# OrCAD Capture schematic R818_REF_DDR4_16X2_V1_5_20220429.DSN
size A3; title: R818-DDR4; rev: 0.1; note: DDR4 16X2
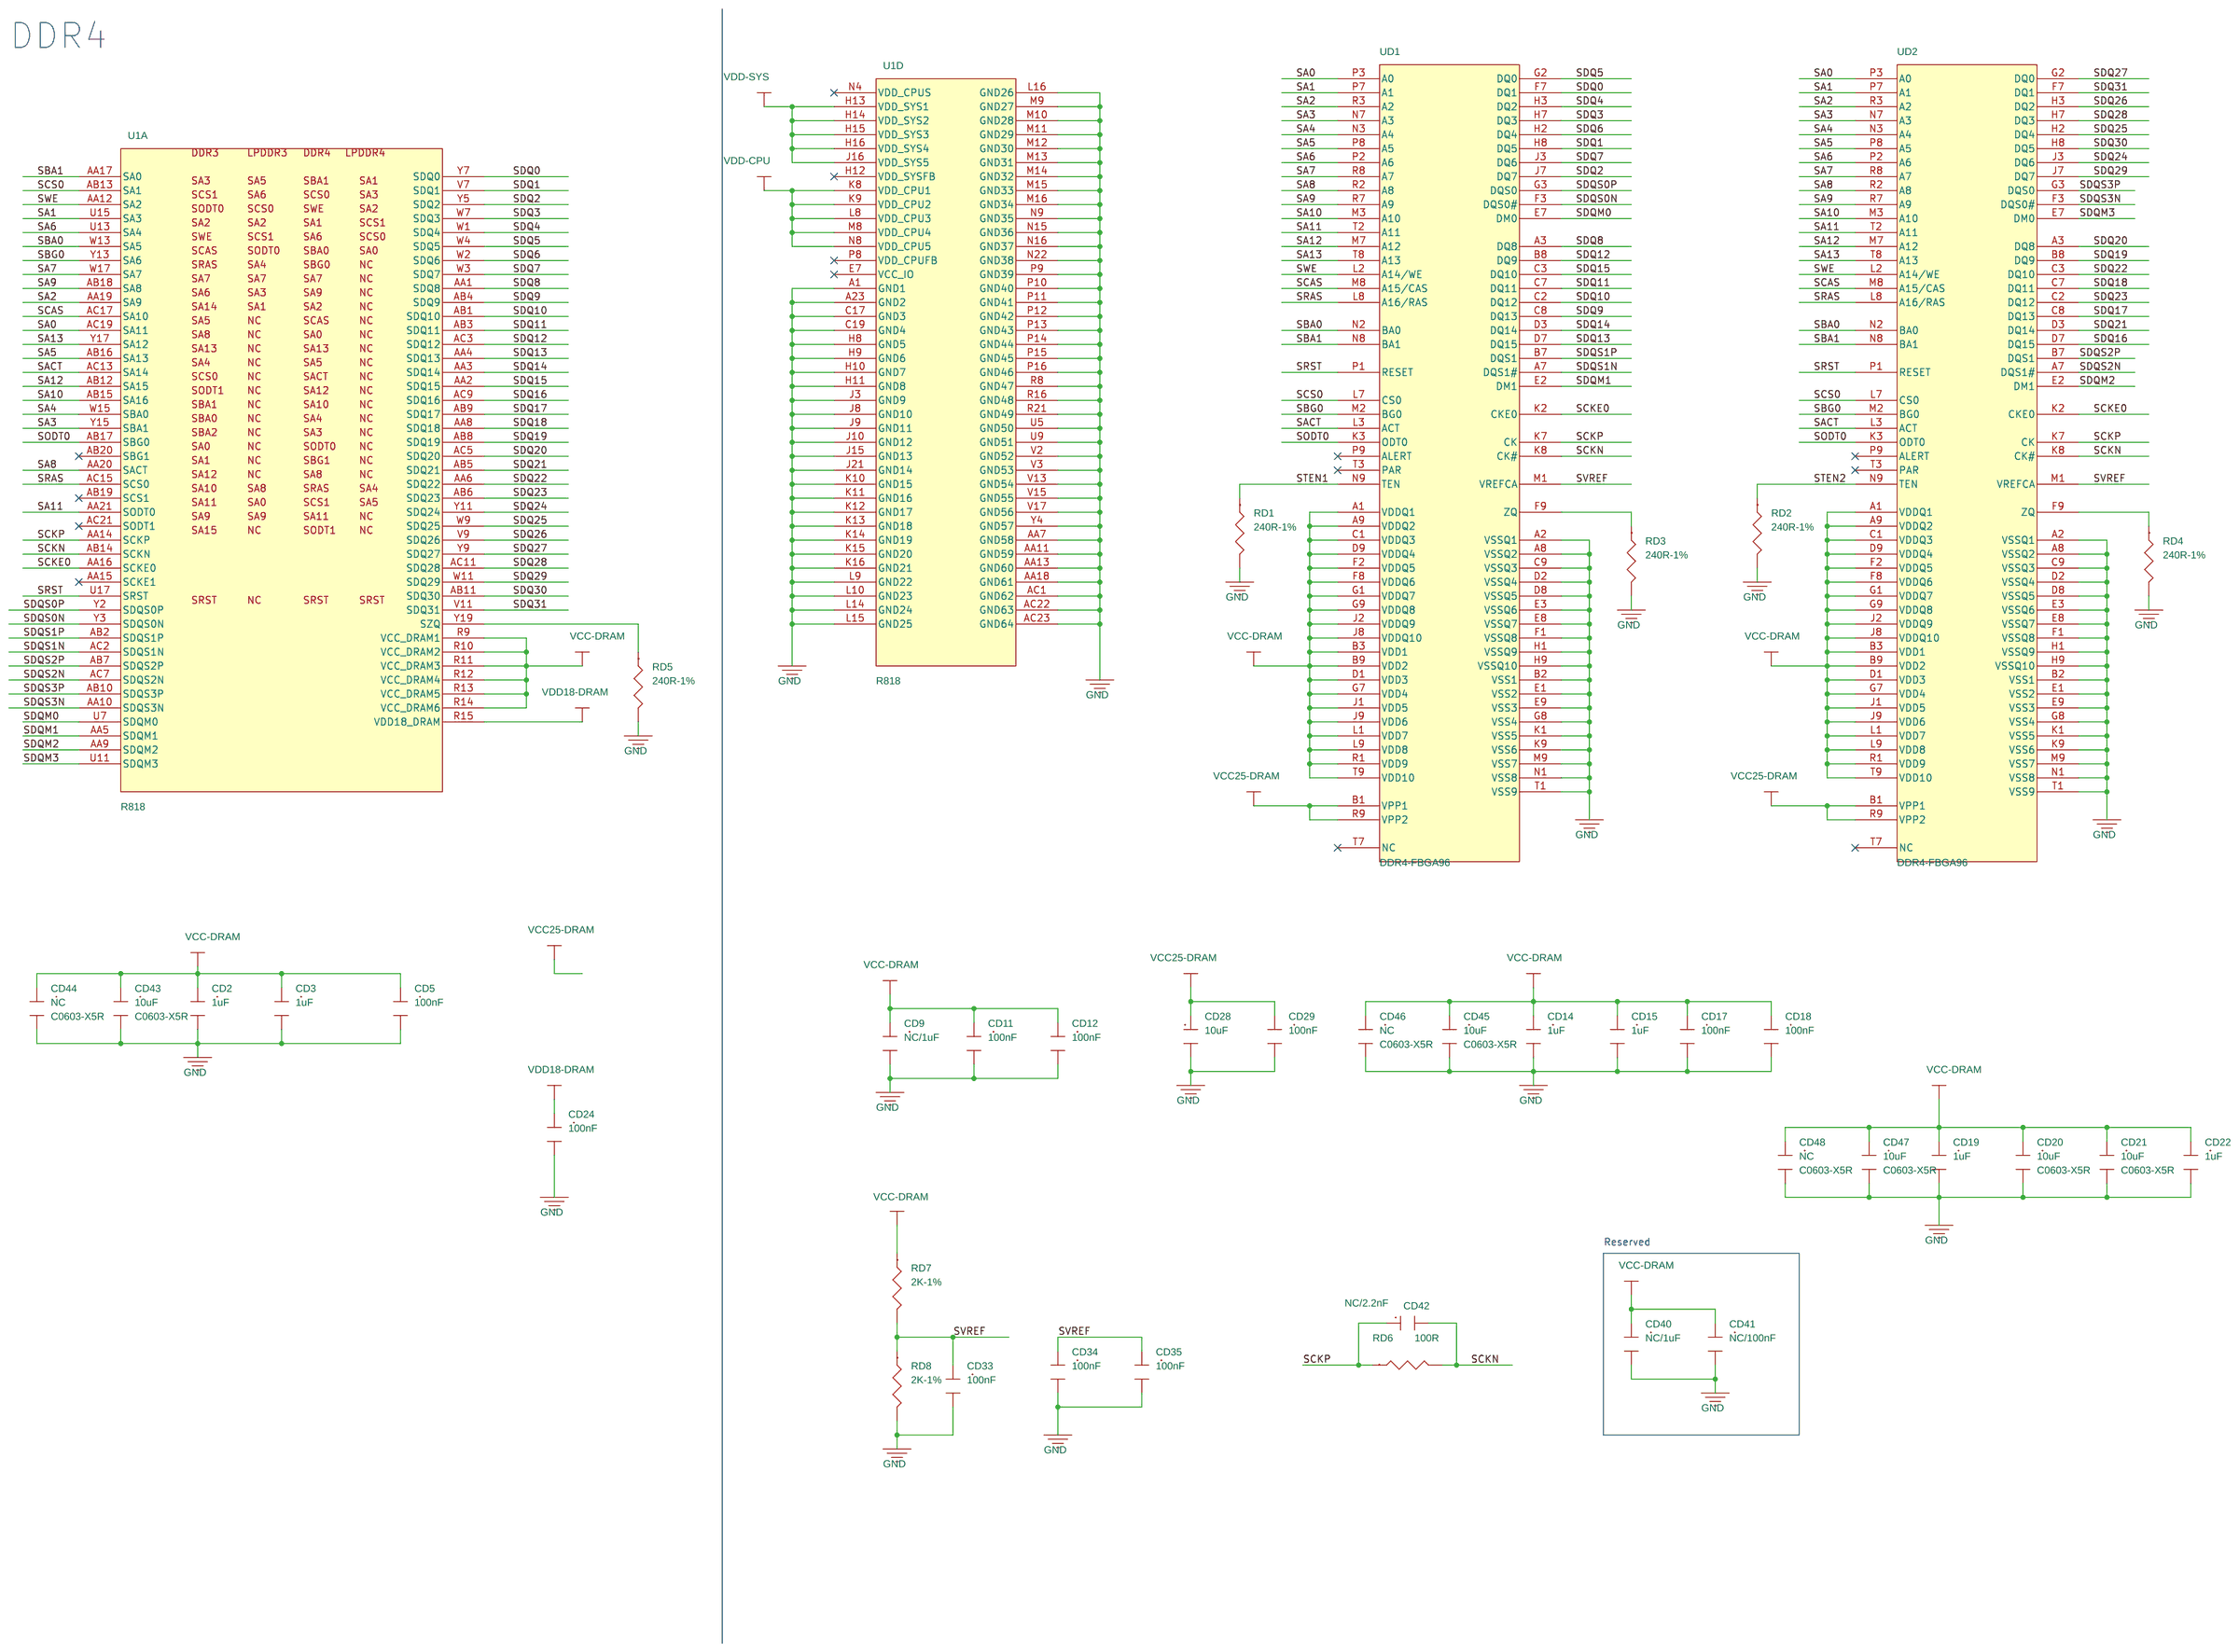
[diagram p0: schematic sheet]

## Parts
CD2  1uF  [C0402]
CD3  1uF  [C0402]
CD5  100nF  [C0402]
CD9  NC/1uF  [C0402]
CD11  100nF  [C0402]
CD12  100nF  [C0402]
CD14  1uF  [C0402]
CD15  1uF  [C0402]
CD17  100nF  [C0402]
CD18  100nF  [C0402]
CD19  1uF  [C0402]
CD20  10uF  [C0603]
CD21  10uF  [C0603]
CD22  1uF  [C0402]
CD24  100nF  [C0402]
CD28  10uF  [C0603]
CD29  100nF  [C0402]
CD33  100nF  [C0402]
CD34  100nF  [C0402]
CD35  100nF  [C0402]
CD40  NC/1uF  [C0402]
CD41  NC/100nF  [C0402]
CD42  NC/2.2nF  [C0402]
CD43  10uF  [C0603]
CD44  NC  [C0603]
CD45  10uF  [C0603]
CD46  NC  [C0603]
CD47  10uF  [C0603]
CD48  NC  [C0603]
RD1  240R-1%  [R0402]
RD2  240R-1%  [R0402]
RD3  240R-1%  [R0402]
RD4  240R-1%  [R0402]
RD5  240R-1%  [R0402]
RD6  100R  [R0402]
RD7  2K-1%  [R0402]
RD8  2K-1%  [R0402]
U1  R818  [BGA346P50B1200_1200H114]  (sections A,D)
UD1  DDR4-FBGA96  [BGA96P80B1000_1400H120]
UD2  DDR4-FBGA96  [BGA96P80B1000_1400H120]

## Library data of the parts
CD2 CD3 CD5 CD9 CD11 CD12 CD14 CD15 CD17-CD19 CD22 CD24 CD29 CD33-CD35 CD40-CD42 = C-C0402-X5R
CD20 CD21 CD43-CD48 = C-C0402-X5R: Parameter: C0603-X5R
CD28 = C-C0603-X5R
RD1-RD5 RD7 RD8 = R-R0402-1%
RD6 = R-R0402-5%
U1 = R818-BGA-20200509
UD1 UD2 = DDR4-FBGA96

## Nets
GND: CD2.2 CD3.2 CD5.2 CD9.2 CD11.2 CD12.2 CD14.2 CD15.2 CD17.2 CD18.2 CD19.2 CD20.2 CD21.2 CD22.2 CD24.2 CD28.2 CD29.2 CD33.2 CD34.2 CD35.2 CD40.2 CD41.2 CD43.2 CD44.2 CD45.2 CD46.2 CD47.2 CD48.2 RD1.2 RD2.2 RD3.2 RD4.2 RD5.2 RD8.2 U1.A1(GND1) U1.A23(GND2) U1.AA7(GND58) U1.AA11(GND59) U1.AA13(GND60) U1.AA18(GND61) U1.AC1(GND62) U1.AC22(GND63) U1.AC23(GND64) U1.C17(GND3) U1.C19(GND4) U1.H8(GND5) U1.H9(GND6) U1.H10(GND7) U1.H11(GND8) U1.J3(GND9) U1.J8(GND10) U1.J9(GND11) U1.J10(GND12) U1.J15(GND13) U1.J21(GND14) U1.K10(GND15) U1.K11(GND16) U1.K12(GND17) U1.K13(GND18) U1.K14(GND19) U1.K15(GND20) U1.K16(GND21) U1.L9(GND22) U1.L10(GND23) U1.L14(GND24) U1.L15(GND25) U1.L16(GND26) U1.M9(GND27) U1.M10(GND28) U1.M11(GND29) U1.M12(GND30) U1.M13(GND31) U1.M14(GND32) U1.M15(GND33) U1.M16(GND34) U1.N9(GND35) U1.N15(GND36) U1.N16(GND37) U1.N22(GND38) U1.P9(GND39) U1.P10(GND40) U1.P11(GND41) U1.P12(GND42) U1.P13(GND43) U1.P14(GND44) U1.P15(GND45) U1.P16(GND46) U1.R8(GND47) U1.R16(GND48) U1.R21(GND49) U1.U5(GND50) U1.U9(GND51) U1.V2(GND52) U1.V3(GND53) U1.V13(GND54) U1.V15(GND55) U1.V17(GND56) U1.Y4(GND57) UD1.A2(VSSQ1) UD1.A8(VSSQ2) UD1.B2(VSS1) UD1.C9(VSSQ3) UD1.D2(VSSQ4) UD1.D8(VSSQ5) UD1.E1(VSS2) UD1.E3(VSSQ6) UD1.E8(VSSQ7) UD1.E9(VSS3) UD1.F1(VSSQ8) UD1.G8(VSS4) UD1.H1(VSSQ9) UD1.H9(VSSQ10) UD1.K1(VSS5) UD1.K9(VSS6) UD1.M9(VSS7) UD1.N1(VSS8) UD1.T1(VSS9) UD2.A2(VSSQ1) UD2.A8(VSSQ2) UD2.B2(VSS1) UD2.C9(VSSQ3) UD2.D2(VSSQ4) UD2.D8(VSSQ5) UD2.E1(VSS2) UD2.E3(VSSQ6) UD2.E8(VSSQ7) UD2.E9(VSS3) UD2.F1(VSSQ8) UD2.G8(VSS4) UD2.H1(VSSQ9) UD2.H9(VSSQ10) UD2.K1(VSS5) UD2.K9(VSS6) UD2.M9(VSS7) UD2.N1(VSS8) UD2.T1(VSS9)
VCC25-DRAM: CD28.1 CD29.1 UD1.B1(VPP1) UD1.R9(VPP2) UD2.B1(VPP1) UD2.R9(VPP2)
VCC-DRAM: CD2.1 CD3.1 CD5.1 CD9.1 CD11.1 CD12.1 CD14.1 CD15.1 CD17.1 CD18.1 CD19.1 CD20.1 CD21.1 CD22.1 CD40.1 CD41.1 CD43.1 CD44.1 CD45.1 CD46.1 CD47.1 CD48.1 RD7.1 U1.R9(VCC_DRAM1) U1.R10(VCC_DRAM2) U1.R11(VCC_DRAM3) U1.R12(VCC_DRAM4) U1.R13(VCC_DRAM5) U1.R14(VCC_DRAM6) UD1.A1(VDDQ1) UD1.A9(VDDQ2) UD1.B3(VDD1) UD1.B9(VDD2) UD1.C1(VDDQ3) UD1.D1(VDD3) UD1.D9(VDDQ4) UD1.F2(VDDQ5) UD1.F8(VDDQ6) UD1.G1(VDDQ7) UD1.G7(VDD4) UD1.G9(VDDQ8) UD1.J1(VDD5) UD1.J2(VDDQ9) UD1.J8(VDDQ10) UD1.J9(VDD6) UD1.L1(VDD7) UD1.L9(VDD8) UD1.R1(VDD9) UD1.T9(VDD10) UD2.A1(VDDQ1) UD2.A9(VDDQ2) UD2.B3(VDD1) UD2.B9(VDD2) UD2.C1(VDDQ3) UD2.D1(VDD3) UD2.D9(VDDQ4) UD2.F2(VDDQ5) UD2.F8(VDDQ6) UD2.G1(VDDQ7) UD2.G7(VDD4) UD2.G9(VDDQ8) UD2.J1(VDD5) UD2.J2(VDDQ9) UD2.J8(VDDQ10) UD2.J9(VDD6) UD2.L1(VDD7) UD2.L9(VDD8) UD2.R1(VDD9) UD2.T9(VDD10)
VDD18-DRAM: CD24.1 U1.R15(VDD18_DRAM)
VDD-CPU: U1.K8(VDD_CPU1) U1.K9(VDD_CPU2) U1.L8(VDD_CPU3) U1.M8(VDD_CPU4) U1.N8(VDD_CPU5)
VDD-SYS: U1.H13(VDD_SYS1) U1.H14(VDD_SYS2) U1.H15(VDD_SYS3) U1.H16(VDD_SYS4) U1.J16(VDD_SYS5)
SA0: U1.AC19(SA11) UD1.P3(A0) UD2.P3(A0)
SA1: U1.U15(SA3) UD1.P7(A1) UD2.P7(A1)
SA2: U1.AA19(SA9) UD1.R3(A2) UD2.R3(A2)
SA3: U1.Y15(SBA1) UD1.N7(A3) UD2.N7(A3)
SA4: U1.W15(SBA0) UD1.N3(A4) UD2.N3(A4)
SA5: U1.AB16(SA13) UD1.P8(A5) UD2.P8(A5)
SA6: U1.U13(SA4) UD1.P2(A6) UD2.P2(A6)
SA7: U1.W17(SA7) UD1.R8(A7) UD2.R8(A7)
SA8: U1.AA20(SACT) UD1.R2(A8) UD2.R2(A8)
SA9: U1.AB18(SA8) UD1.R7(A9) UD2.R7(A9)
SA10: U1.AB15(SA16) UD1.M3(A10) UD2.M3(A10)
SA11: U1.AA21(SODT0) UD1.T2(A11) UD2.T2(A11)
SA12: U1.AB12(SA15) UD1.M7(A12) UD2.M7(A12)
SA13: U1.Y17(SA12) UD1.T8(A13) UD2.T8(A13)
SACT: U1.AC13(SA14) UD1.L3(ACT) UD2.L3(ACT)
SBA0: U1.W13(SA5) UD1.N2(BA0) UD2.N2(BA0)
SBA1: U1.AA17(SA0) UD1.N8(BA1) UD2.N8(BA1)
SBG0: U1.Y13(SA6) UD1.M2(BG0) UD2.M2(BG0)
SCAS: U1.AC17(SA10) UD1.M8(A15/CAS) UD2.M8(A15/CAS)
SCKE0: U1.AA16(SCKE0) UD1.K2(CKE0) UD2.K2(CKE0)
SCKN: CD42.2 RD6.2 U1.AB14(SCKN) UD1.K8(CK#) UD2.K8(CK#)
SCKP: CD42.1 RD6.1 U1.AA14(SCKP) UD1.K7(CK) UD2.K7(CK)
SCS0: U1.AB13(SA1) UD1.L7(CS0) UD2.L7(CS0)
SDQ0: U1.Y7(SDQ0) UD1.F7(DQ1)
SDQ1: U1.V7(SDQ1) UD1.H8(DQ5)
SDQ2: U1.Y5(SDQ2) UD1.J7(DQ7)
SDQ3: U1.W7(SDQ3) UD1.H7(DQ3)
SDQ4: U1.W1(SDQ4) UD1.H3(DQ2)
SDQ5: U1.W4(SDQ5) UD1.G2(DQ0)
SDQ6: U1.W2(SDQ6) UD1.H2(DQ4)
SDQ7: U1.W3(SDQ7) UD1.J3(DQ6)
SDQ8: U1.AA1(SDQ8) UD1.A3(DQ8)
SDQ9: U1.AB4(SDQ9) UD1.C8(DQ13)
SDQ10: U1.AB1(SDQ10) UD1.C2(DQ12)
SDQ11: U1.AB3(SDQ11) UD1.C7(DQ11)
SDQ12: U1.AC3(SDQ12) UD1.B8(DQ9)
SDQ13: U1.AA4(SDQ13) UD1.D7(DQ15)
SDQ14: U1.AA3(SDQ14) UD1.D3(DQ14)
SDQ15: U1.AA2(SDQ15) UD1.C3(DQ10)
SDQ16: U1.AC9(SDQ16) UD2.D7(DQ15)
SDQ17: U1.AB9(SDQ17) UD2.C8(DQ13)
SDQ18: U1.AA8(SDQ18) UD2.C7(DQ11)
SDQ19: U1.AB8(SDQ19) UD2.B8(DQ9)
SDQ20: U1.AC5(SDQ20) UD2.A3(DQ8)
SDQ21: U1.AB5(SDQ21) UD2.D3(DQ14)
SDQ22: U1.AA6(SDQ22) UD2.C3(DQ10)
SDQ23: U1.AB6(SDQ23) UD2.C2(DQ12)
SDQ24: U1.Y11(SDQ24) UD2.J3(DQ6)
SDQ25: U1.W9(SDQ25) UD2.H2(DQ4)
SDQ26: U1.V9(SDQ26) UD2.H3(DQ2)
SDQ27: U1.Y9(SDQ27) UD2.G2(DQ0)
SDQ28: U1.AC11(SDQ28) UD2.H7(DQ3)
SDQ29: U1.W11(SDQ29) UD2.J7(DQ7)
SDQ30: U1.AB11(SDQ30) UD2.H8(DQ5)
SDQ31: U1.V11(SDQ31) UD2.F7(DQ1)
SDQM0: U1.U7(SDQM0) UD1.E7(DM0)
SDQM1: U1.AA5(SDQM1) UD1.E2(DM1)
SDQM2: U1.AA9(SDQM2) UD2.E2(DM1)
SDQM3: U1.U11(SDQM3) UD2.E7(DM0)
SDQS0N: U1.Y3(SDQS0N) UD1.F3(DQS0#)
SDQS0P: U1.Y2(SDQS0P) UD1.G3(DQS0)
SDQS1N: U1.AC2(SDQS1N) UD1.A7(DQS1#)
SDQS1P: U1.AB2(SDQS1P) UD1.B7(DQS1)
SDQS2N: U1.AC7(SDQS2N) UD2.A7(DQS1#)
SDQS2P: U1.AB7(SDQS2P) UD2.B7(DQS1)
SDQS3N: U1.AA10(SDQS3N) UD2.F3(DQS0#)
SDQS3P: U1.AB10(SDQS3P) UD2.G3(DQS0)
SODT0: U1.AB17(SBG0) UD1.K3(ODT0) UD2.K3(ODT0)
SRAS: U1.AC15(SCS0) UD1.L8(A16/RAS) UD2.L8(A16/RAS)
SRST: U1.U17(SRST) UD1.P1(RESET) UD2.P1(RESET)
STEN1: RD1.1 UD1.N9(TEN)
STEN2: RD2.1 UD2.N9(TEN)
SVREF: CD33.1 CD34.1 CD35.1 RD7.2 RD8.1 UD1.M1(VREFCA) UD2.M1(VREFCA)
SWE: U1.AA12(SA2) UD1.L2(A14/WE) UD2.L2(A14/WE)
N16281101: RD5.1 U1.Y19(SZQ)
N17928021: RD3.1 UD1.F9(ZQ)
N17931224: RD4.1 UD2.F9(ZQ)

Not connected (* = marked no-connect by the designer): U1 AA15(SCKE1)* AB19(SCS1)* AB20(SBG1)* AC21(SODT1)* E7(VCC_IO)* H12(VDD_SYSFB)* N4(VDD_CPUS)* P8(VDD_CPUFB)*; UD1 P9(ALERT)* T3(PAR)* T7(NC)*; UD2 P9(ALERT)* T3(PAR)* T7(NC)*

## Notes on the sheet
- DDR4
- Reserved
